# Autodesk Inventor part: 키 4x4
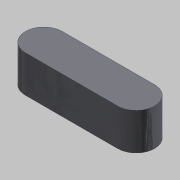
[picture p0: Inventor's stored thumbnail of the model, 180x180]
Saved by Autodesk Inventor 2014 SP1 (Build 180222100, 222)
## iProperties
Created: 2016-04
Part Number: 키 4x4
Document SubType Name: Modeling
Designer: mdu
Density: 7.86 g/cm^3
Mass: 1.65269 g
Surface Area: 2.35398 cm^2
Volume: 0.210265 cm^3
Material: 강철, 연강
Appearance: 강철 - 광택
Author: mdu
Revision Number: 1
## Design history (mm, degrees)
sketch "스케치1"
  geometry: L1 (-5, -2)-(5, -2); L2 (5, 2)-(-5, 2); A1 r 2 centre (5, 0) between (5, -2) and (5, 2); A2 r 2 centre (-5, 0) between (-5, 2) and (-5, -2); 2 further points
  constraints: 4 end point, 4 point on circle, 4 tangent, 2 centre point, 1 horizontal, 1 horizontal alignment, 1 midpoint, 1 parallel, 1 vertical alignment
  dimensions: "d0" = 4 distance between parallel lines of L1 L2; "d1" = 14 dimension on A1 A2
extrude "돌출1" new body sketch "스케치1" stored distance "d2" = 4; taper "d3" = 0 deg
node "솔리드1"
